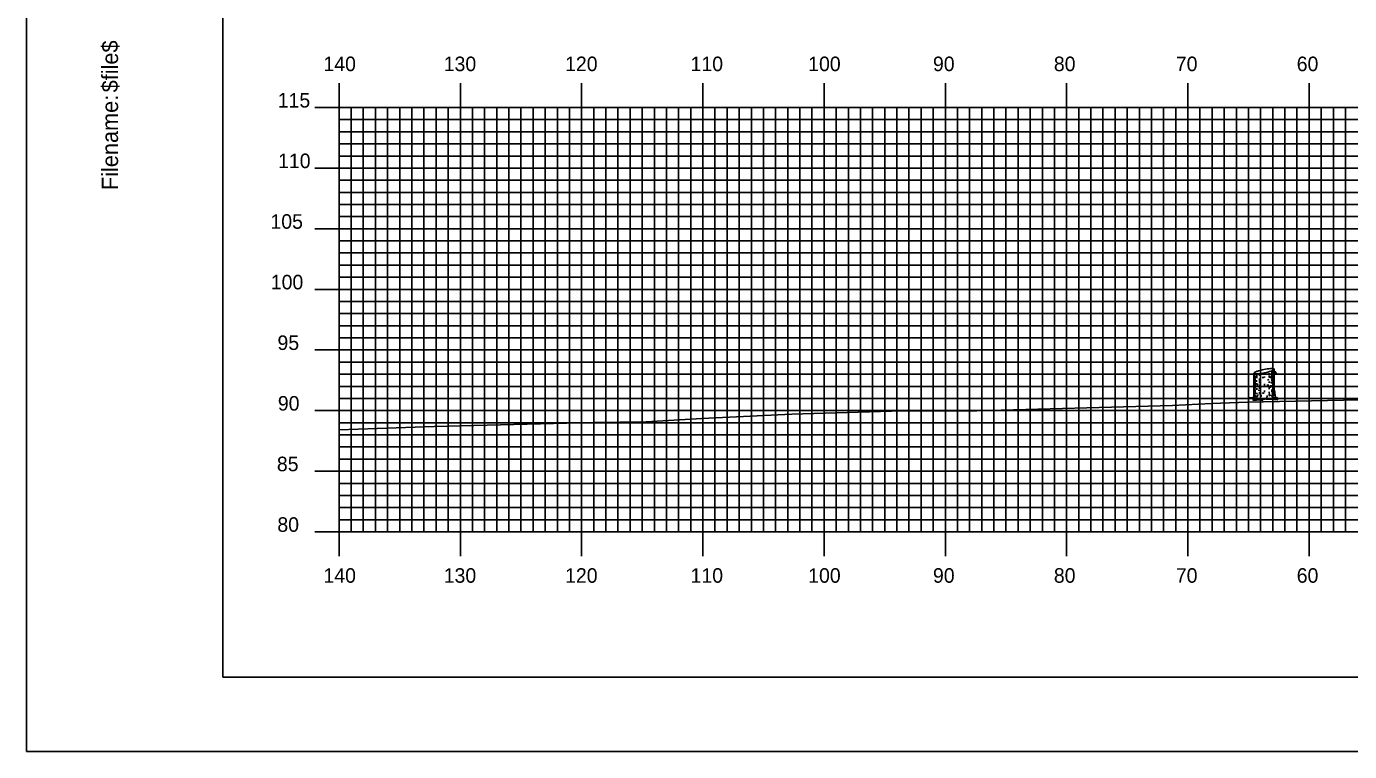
# Model space of a CAD drawing. Extents: x 1760610 to 1760954, y 442591 to 442811.
# Drawn here: x 1760610.4 to 1760719.5, y 442590.5 to 442650.4 of the extents above; entities that cross this region are included whole.
import ezdxf

# ---------------------------------------------------------------- set-up
doc = ezdxf.new("R2010")
doc.units = 0
for name, color, linetype in [('BORDER', 7, 'Continuous'), ('H_V ANNOTATION', 7, 'Continuous'), ('M_Trees_Conifer_Pay', 7, 'Continuous'), ('MAJOR', 7, 'Continuous'), ('MINOR', 7, 'Continuous'), ('PLOT BOUNDARY', 7, 'Continuous'), ('S_Roadway_Centerline', 7, 'Continuous')]:
    doc.layers.add(name, color=color, linetype=linetype)

msp = doc.modelspace()

# ---------------------------------------------------------------- linework, layer by layer
at = {"layer": 'BORDER'}
msp.add_lwpolyline([(1760626.61, 442596.67), (1760946.61, 442596.67), (1760946.61, 442806.67), (1760626.61, 442806.67)], close=True, dxfattribs=at)
at = {"layer": 'M_Trees_Conifer_Pay'}
for p, q in [((1760713.26, 442622.01), (1760713.26, 442621.85)), ((1760713.33, 442620.44), (1760713.33, 442622.09)), ((1760711.66, 442620.03), (1760711.66, 442621.75)), ((1760711.71, 442621.71), (1760711.71, 442621.24)), ((1760711.71, 442621.18), (1760711.71, 442620.87)), ((1760711.77, 442621.7), (1760711.77, 442621.61)), ((1760711.77, 442621.53), (1760711.77, 442621.33)), ((1760711.77, 442621.27), (1760711.77, 442621.07)), ((1760711.77, 442621.02), (1760711.77, 442620.69)), ((1760711.89, 442621.7), (1760711.89, 442621.46)), ((1760711.89, 442621.42), (1760711.89, 442621.35)), ((1760711.89, 442620.94), (1760711.89, 442620.81)), ((1760712.11, 442621.72), (1760712.11, 442621.55)), ((1760712.11, 442621.31), (1760712.11, 442621.07)), ((1760712.52, 442621.48), (1760712.52, 442621.39)), ((1760712.91, 442621.76), (1760712.91, 442621.56)), ((1760712.91, 442621.5), (1760712.91, 442621.41)), ((1760712.91, 442621.06), (1760712.91, 442620.96)), ((1760713.14, 442621.95), (1760713.14, 442621.73)), ((1760713.14, 442621.64), (1760713.14, 442621.59)), ((1760713.2, 442621.46), (1760713.14, 442621.4)), ((1760713.14, 442621.26), (1760713.14, 442621.13)), ((1760713.14, 442621.02), (1760713.14, 442620.91)), ((1760713.26, 442621.78), (1760713.26, 442621.66)), ((1760713.26, 442621.47), (1760713.26, 442621.13)), ((1760713.26, 442621.1), (1760713.26, 442620.93)), ((1760713.26, 442620.89), (1760713.26, 442620.67)), ((1760711.71, 442620.82), (1760711.71, 442620.33)), ((1760711.71, 442620.28), (1760711.71, 442620.03)), ((1760711.77, 442620.63), (1760711.77, 442620.5)), ((1760711.77, 442620.4), (1760711.77, 442620.02)), ((1760711.89, 442620.53), (1760711.89, 442620.39)), ((1760711.89, 442620.13), (1760711.89, 442620.04)), ((1760712.11, 442620.83), (1760712.11, 442620.68)), ((1760712.11, 442620.63), (1760712.11, 442620.46)), ((1760712.11, 442620.18), (1760712.11, 442620.03)), ((1760712.52, 442620.87), (1760712.52, 442620.8)), ((1760712.52, 442620.77), (1760712.52, 442620.62)), ((1760712.52, 442620.33), (1760712.52, 442620.18)), ((1760712.91, 442620.59), (1760712.91, 442620.45)), ((1760712.91, 442620.21), (1760712.91, 442620.12)), ((1760713.14, 442620.77), (1760713.14, 442620.63)), ((1760713.14, 442620.4), (1760713.14, 442620.23)), ((1760713.26, 442620.64), (1760713.26, 442620.57)), ((1760713.26, 442620.52), (1760713.26, 442620.35)), ((1760711.89, 442619.64), (1760712.06, 442619.7)), ((1760712.33, 442619.57), (1760712.21, 442619.64))]:
    msp.add_line(p, q, dxfattribs=at)
for points in [[(1760711.84, 442621.06), (1760711.84, 442621.15), (1760711.88, 442621.13), (1760711.88, 442621.04)], [(1760713.11, 442621.55), (1760713.08, 442621.46), (1760713.08, 442621.4), (1760713.11, 442621.33)], [(1760713.14, 442621.58), (1760713.18, 442621.51), (1760713.23, 442621.57), (1760713.29, 442621.64), (1760713.38, 442621.83), (1760713.44, 442621.88), (1760713.47, 442621.88)], [(1760713.16, 442621.33), (1760713.2, 442621.46), (1760713.26, 442621.57), (1760713.29, 442621.64), (1760713.36, 442621.79)], [(1760713.37, 442621.82), (1760713.45, 442621.83), (1760713.52, 442621.73)], [(1760713.33, 442620.44), (1760713.38, 442620.18), (1760713.4, 442619.9), (1760713.45, 442619.78), (1760713.59, 442619.75), (1760713.36, 442619.71), (1760713.36, 442619.71), (1760713.36, 442619.66), (1760713.61, 442619.57), (1760713.34, 442619.59), (1760712.98, 442619.61), (1760712.66, 442619.6), (1760712.67, 442619.68), (1760712.52, 442619.6), (1760712.33, 442619.57), (1760712.36, 442619.5), (1760712.09, 442619.55), (1760711.87, 442619.52), (1760711.58, 442619.54), (1760711.86, 442619.6), (1760711.89, 442619.64), (1760711.73, 442619.69), (1760711.5, 442619.71), (1760711.25, 442619.71), (1760711.6, 442619.76), (1760711.64, 442619.84), (1760711.66, 442620.03)], [(1760711.71, 442619.98), (1760711.69, 442619.9), (1760711.67, 442619.81)], [(1760711.79, 442619.96), (1760711.8, 442619.85), (1760711.74, 442619.76), (1760711.73, 442619.69)], [(1760711.95, 442619.99), (1760711.95, 442619.86), (1760711.86, 442619.76)], [(1760712.18, 442619.75), (1760712.25, 442619.84), (1760712.27, 442619.98)], [(1760712.67, 442619.68), (1760712.74, 442619.82), (1760712.75, 442619.92)], [(1760712.92, 442620.05), (1760712.93, 442619.92), (1760713, 442619.88)], [(1760712.98, 442620.66), (1760712.99, 442620.58), (1760713.04, 442620.59), (1760713.03, 442620.76)], [(1760713.2, 442619.66), (1760713.18, 442619.8), (1760713.11, 442619.92)], [(1760713.15, 442620.15), (1760713.23, 442620.05), (1760713.23, 442619.87), (1760713.36, 442619.71)], [(1760713.25, 442620.3), (1760713.26, 442620.15), (1760713.31, 442620.08), (1760713.32, 442619.88)]]:
    msp.add_lwpolyline(points, dxfattribs=at)
for centre, radius, start, end in [((1760713.52, 442616.98), 5.18, 101.7194, 108.0594), ((1760713.52, 442616.98), 5.18, 95.3794, 101.7194), ((1760713.11, 442621.34), 0.802, 79.2194, 95.3794), ((1760712.83, 442622.69), 0.802, 288.0594, 304.2194), ((1760713.21, 442621.88), 0.251, 71.0501, 79.2194), ((1760713.14, 442622.24), 0.251, 304.2194, 312.3887), ((1760713.27, 442622.04), 0.0817, 56.7194, 71.0501), ((1760713.28, 442622.07), 0.0527, 46.923, 56.7194), ((1760713.25, 442622.11), 0.0817, 312.3887, 326.7194), ((1760713.3, 442622.08), 0.0314, 34.2194, 46.923), ((1760713.3, 442622.09), 0.0264, 23.4074, 34.2194), ((1760713.28, 442622.1), 0.0527, 326.7194, 336.5158), ((1760713.31, 442622.09), 0.0226, 11.7194, 23.4074), ((1760713.3, 442622.09), 0.0264, 349.2194, 0.0315), ((1760713.31, 442622.09), 0.0226, 0.0315, 11.7194), ((1760713.3, 442622.09), 0.0314, 336.5158, 349.2194), ((1760711.7, 442621.75), 0.0314, 156.5158, 169.2194), ((1760711.69, 442621.75), 0.0264, 169.2194, 180.0315), ((1760711.69, 442621.75), 0.0226, 180.0315, 191.7194), ((1760711.69, 442621.75), 0.0226, 191.7194, 203.4074), ((1760711.7, 442621.57), 0.0334, 163.9485, 180), ((1760711.7, 442621.57), 0.0334, 180, 196.0515), ((1760711.71, 442621.58), 0.0441, 196.0515, 210), ((1760711.7, 442621.13), 0.0334, 163.9485, 180), ((1760711.7, 442621.13), 0.0334, 180, 196.0515), ((1760711.71, 442621.13), 0.0441, 196.0515, 210), ((1760711.7, 442620.92), 0.0334, 163.9485, 180), ((1760711.7, 442620.92), 0.0334, 180, 196.0515), ((1760711.71, 442620.92), 0.0441, 196.0515, 210), ((1760711.74, 442621.73), 0.0817, 132.3887, 146.7194), ((1760711.72, 442621.74), 0.0527, 146.7194, 156.5158), ((1760711.69, 442621.75), 0.0264, 203.4074, 214.2194), ((1760711.69, 442621.76), 0.0314, 214.2194, 226.923), ((1760711.71, 442621.77), 0.0527, 226.923, 236.7194), ((1760711.72, 442621.59), 0.0624, 210, 228.7494), ((1760711.72, 442621.14), 0.0624, 210, 228.7494), ((1760711.72, 442620.93), 0.0624, 210, 228.7494), ((1760711.85, 442621.6), 0.251, 124.2194, 132.3887), ((1760711.72, 442621.8), 0.0817, 236.7194, 251.0501), ((1760711.79, 442621.67), 0.172, 228.7494, 240), ((1760711.79, 442621.22), 0.172, 228.7494, 240), ((1760711.78, 442621.96), 0.251, 251.0501, 259.2194), ((1760712.16, 442621.15), 0.802, 108.0594, 124.2194), ((1760711.99, 442622.01), 0.571, 240, 240.3367), ((1760712, 442621.8), 0.571, 240, 247.0587), ((1760711.99, 442621.57), 0.571, 240, 240.3367), ((1760711.88, 442622.5), 0.802, 259.2194, 275.3794), ((1760711.99, 442622.01), 0.571, 246.8597, 257.9846), ((1760711.47, 442626.85), 5.18, 275.3794, 281.7194), ((1760712.49, 442625.08), 4.12, 264.081, 266.6676), ((1760712.5, 442625.76), 4.12, 264.6955, 266.7331), ((1760712.49, 442625.53), 4.12, 268.0751, 270), ((1760712.49, 442625.53), 4.12, 270, 270.3581), ((1760711.47, 442626.85), 5.18, 281.7194, 288.0594), ((1760712.5, 442625.32), 4.12, 273.7052, 275.9504), ((1760712.49, 442625.53), 4.12, 275.7849, 277.0558), ((1760712.5, 442625.76), 4.12, 276.238, 278.1032), ((1760712.49, 442625.08), 4.12, 277.6125, 278.1032), ((1760713, 442622.25), 0.571, 278.1032, 284.3667), ((1760713, 442621.57), 0.571, 278.1032, 286.9296), ((1760713, 442622.4), 0.571, 284.4317, 292.4132), ((1760713, 442621.8), 0.571, 284.4493, 297.0429), ((1760713, 442622.25), 0.571, 297.0237, 300), ((1760713, 442621.57), 0.571, 297.1896, 300), ((1760713.2, 442622.06), 0.172, 300, 311.2506), ((1760713.2, 442621.9), 0.172, 300, 311.2506), ((1760713.19, 442621.22), 0.172, 300, 311.2506), ((1760713.27, 442621.97), 0.0624, 311.2506, 330), ((1760713.27, 442621.82), 0.0624, 311.2506, 330), ((1760713.27, 442621.14), 0.0624, 311.2506, 330), ((1760713.27, 442620.93), 0.0624, 311.2506, 330), ((1760713.28, 442621.96), 0.0441, 330, 343.9485), ((1760713.28, 442621.81), 0.0441, 330, 343.9485), ((1760713.28, 442621.13), 0.0441, 330, 343.9485), ((1760713.28, 442620.92), 0.0441, 330, 343.9485), ((1760713.29, 442621.96), 0.0334, 343.9485, 354.2151), ((1760713.29, 442621.81), 0.0334, 343.9485, 354.2151), ((1760713.29, 442621.36), 0.0334, 343.9485, 354.2151), ((1760713.29, 442621.13), 0.0334, 343.9485, 354.2151), ((1760713.29, 442620.92), 0.0334, 343.9485, 354.2151), ((1760711.7, 442620.68), 0.0334, 163.9485, 180), ((1760711.7, 442620.68), 0.0334, 180, 196.0515), ((1760711.71, 442620.68), 0.0441, 196.0515, 210), ((1760711.7, 442620.48), 0.0334, 163.9485, 180), ((1760711.7, 442620.29), 0.0334, 163.9485, 180), ((1760711.7, 442620.29), 0.0334, 180, 196.0515), ((1760711.71, 442620.29), 0.0441, 196.0515, 210), ((1760711.7, 442620.07), 0.0334, 163.9485, 180), ((1760711.7, 442620.07), 0.0334, 180, 196.0515), ((1760711.71, 442620.07), 0.0441, 196.0515, 210), ((1760711.72, 442620.69), 0.0624, 210, 228.7494), ((1760711.72, 442620.3), 0.0624, 210, 228.7494), ((1760711.72, 442620.08), 0.0624, 210, 228.7494), ((1760711.79, 442621.01), 0.172, 228.7494, 240), ((1760711.79, 442620.77), 0.172, 228.7494, 240), ((1760711.79, 442620.38), 0.172, 228.7494, 240), ((1760711.79, 442620.16), 0.172, 228.7494, 240), ((1760711.99, 442621.36), 0.571, 240, 246.8597), ((1760711.99, 442621.12), 0.571, 240, 246.8597), ((1760711.98, 442620.93), 0.571, 241.2369, 248.0268), ((1760711.99, 442620.73), 0.571, 240, 246.8597), ((1760711.99, 442620.51), 0.571, 240, 244.5314), ((1760711.99, 442621.36), 0.571, 259.2707, 261.8968), ((1760712.49, 442624.87), 4.12, 261.8968, 263.1474), ((1760712.49, 442624.02), 4.12, 262.4438, 263.512), ((1760712.49, 442624.44), 4.12, 263.4991, 265.8397), ((1760712.49, 442624.64), 4.12, 264.716, 266.3193), ((1760712.49, 442624.24), 4.12, 267.8117, 270), ((1760712.49, 442624.87), 4.12, 270, 270.3581), ((1760712.49, 442624.24), 4.12, 270, 270.1328), ((1760712.49, 442624.87), 4.12, 273.1493, 275.4569), ((1760712.49, 442624.24), 4.12, 275.7849, 276.7896), ((1760712.49, 442624.02), 4.12, 277.3684, 278.1032), ((1760713, 442620.51), 0.571, 278.1032, 281.637), ((1760713, 442621.12), 0.571, 285.3983, 297.1896), ((1760713, 442620.92), 0.571, 289.2907, 300), ((1760713, 442620.73), 0.571, 288.5067, 297.2721), ((1760713, 442621.36), 0.571, 297.1896, 300), ((1760713.19, 442621.01), 0.172, 300, 311.2506), ((1760713.19, 442620.58), 0.172, 300, 311.2506), ((1760713.19, 442620.16), 0.172, 300, 311.2506), ((1760713.27, 442620.49), 0.0624, 311.2506, 330), ((1760713.27, 442620.08), 0.0624, 311.2506, 330), ((1760713.28, 442620.49), 0.0441, 330, 343.9485), ((1760713.28, 442620.07), 0.0441, 330, 343.9485), ((1760713.29, 442620.48), 0.0334, 343.9485, 354.2151), ((1760713.29, 442620.07), 0.0334, 343.9485, 354.2151)]:
    msp.add_arc(centre, radius, start, end, dxfattribs=at)
at = {"layer": 'MAJOR'}
for p, q in [((1760636.21, 442645.67), (1760636.21, 442643.67)), ((1760646.21, 442645.67), (1760646.21, 442643.67)), ((1760656.21, 442645.67), (1760656.21, 442643.67)), ((1760666.21, 442645.67), (1760666.21, 442643.67)), ((1760676.21, 442645.67), (1760676.21, 442643.67)), ((1760686.21, 442645.67), (1760686.21, 442643.67)), ((1760696.21, 442645.67), (1760696.21, 442643.67)), ((1760706.21, 442645.67), (1760706.21, 442643.67)), ((1760716.21, 442645.67), (1760716.21, 442643.67)), ((1760634.21, 442643.67), (1760636.21, 442643.67)), ((1760636.21, 442643.67), (1760916.21, 442643.67)), ((1760636.21, 442608.67), (1760636.21, 442643.67)), ((1760636.21, 442608.67), (1760636.21, 442643.67)), ((1760636.21, 442643.67), (1760916.21, 442643.67)), ((1760646.21, 442608.67), (1760646.21, 442643.67)), ((1760656.21, 442608.67), (1760656.21, 442643.67)), ((1760666.21, 442608.67), (1760666.21, 442643.67)), ((1760676.21, 442608.67), (1760676.21, 442643.67)), ((1760686.21, 442608.67), (1760686.21, 442643.67)), ((1760696.21, 442608.67), (1760696.21, 442643.67)), ((1760706.21, 442608.67), (1760706.21, 442643.67)), ((1760716.21, 442608.67), (1760716.21, 442643.67)), ((1760634.21, 442638.67), (1760636.21, 442638.67)), ((1760636.21, 442638.67), (1760916.21, 442638.67)), ((1760634.21, 442633.67), (1760636.21, 442633.67)), ((1760636.21, 442633.67), (1760916.21, 442633.67)), ((1760634.21, 442628.67), (1760636.21, 442628.67)), ((1760636.21, 442628.67), (1760916.21, 442628.67)), ((1760634.21, 442623.67), (1760636.21, 442623.67)), ((1760636.21, 442623.67), (1760916.21, 442623.67)), ((1760634.21, 442618.67), (1760636.21, 442618.67)), ((1760636.21, 442618.67), (1760916.21, 442618.67)), ((1760634.21, 442613.67), (1760636.21, 442613.67)), ((1760636.21, 442613.67), (1760916.21, 442613.67)), ((1760634.21, 442608.67), (1760636.21, 442608.67)), ((1760636.21, 442608.67), (1760916.21, 442608.67)), ((1760636.21, 442608.67), (1760916.21, 442608.67)), ((1760636.21, 442606.66), (1760636.21, 442608.67)), ((1760646.21, 442606.66), (1760646.21, 442608.67)), ((1760656.21, 442606.66), (1760656.21, 442608.67)), ((1760666.21, 442606.66), (1760666.21, 442608.67)), ((1760676.21, 442606.66), (1760676.21, 442608.67)), ((1760686.21, 442606.66), (1760686.21, 442608.67)), ((1760696.21, 442606.66), (1760696.21, 442608.67)), ((1760706.21, 442606.66), (1760706.21, 442608.67)), ((1760716.21, 442606.66), (1760716.21, 442608.67))]:
    msp.add_line(p, q, dxfattribs=at)
at = {"layer": 'MINOR'}
for p, q in [((1760637.21, 442608.67), (1760637.21, 442643.67)), ((1760638.21, 442608.67), (1760638.21, 442643.67)), ((1760639.21, 442608.67), (1760639.21, 442643.67)), ((1760640.21, 442608.67), (1760640.21, 442643.67)), ((1760641.21, 442608.67), (1760641.21, 442643.67)), ((1760642.21, 442608.67), (1760642.21, 442643.67)), ((1760643.21, 442608.67), (1760643.21, 442643.67)), ((1760644.21, 442608.67), (1760644.21, 442643.67)), ((1760645.21, 442608.67), (1760645.21, 442643.67)), ((1760647.21, 442608.67), (1760647.21, 442643.67)), ((1760648.21, 442608.67), (1760648.21, 442643.67)), ((1760649.21, 442608.67), (1760649.21, 442643.67)), ((1760650.21, 442608.67), (1760650.21, 442643.67)), ((1760651.21, 442608.67), (1760651.21, 442643.67)), ((1760652.21, 442608.67), (1760652.21, 442643.67)), ((1760653.21, 442608.67), (1760653.21, 442643.67)), ((1760654.21, 442608.67), (1760654.21, 442643.67)), ((1760655.21, 442608.67), (1760655.21, 442643.67)), ((1760657.21, 442608.67), (1760657.21, 442643.67)), ((1760658.21, 442608.67), (1760658.21, 442643.67)), ((1760659.21, 442608.67), (1760659.21, 442643.67)), ((1760660.21, 442608.67), (1760660.21, 442643.67)), ((1760661.21, 442608.67), (1760661.21, 442643.67)), ((1760662.21, 442608.67), (1760662.21, 442643.67)), ((1760663.21, 442608.67), (1760663.21, 442643.67)), ((1760664.21, 442608.67), (1760664.21, 442643.67)), ((1760665.21, 442608.67), (1760665.21, 442643.67)), ((1760667.21, 442608.67), (1760667.21, 442643.67)), ((1760668.21, 442608.67), (1760668.21, 442643.67)), ((1760669.21, 442608.67), (1760669.21, 442643.67)), ((1760670.21, 442608.67), (1760670.21, 442643.67)), ((1760671.21, 442608.67), (1760671.21, 442643.67)), ((1760672.21, 442608.67), (1760672.21, 442643.67)), ((1760673.21, 442608.67), (1760673.21, 442643.67)), ((1760674.21, 442608.67), (1760674.21, 442643.67)), ((1760675.21, 442608.67), (1760675.21, 442643.67)), ((1760677.21, 442608.67), (1760677.21, 442643.67)), ((1760678.21, 442608.67), (1760678.21, 442643.67)), ((1760679.21, 442608.67), (1760679.21, 442643.67)), ((1760680.21, 442608.67), (1760680.21, 442643.67)), ((1760681.21, 442608.67), (1760681.21, 442643.67)), ((1760682.21, 442608.67), (1760682.21, 442643.67)), ((1760683.21, 442608.67), (1760683.21, 442643.67)), ((1760684.21, 442608.67), (1760684.21, 442643.67)), ((1760685.21, 442608.67), (1760685.21, 442643.67)), ((1760687.21, 442608.67), (1760687.21, 442643.67)), ((1760688.21, 442608.67), (1760688.21, 442643.67)), ((1760689.21, 442608.67), (1760689.21, 442643.67)), ((1760690.21, 442608.67), (1760690.21, 442643.67)), ((1760691.21, 442608.67), (1760691.21, 442643.67)), ((1760692.21, 442608.67), (1760692.21, 442643.67)), ((1760693.21, 442608.67), (1760693.21, 442643.67)), ((1760694.21, 442608.67), (1760694.21, 442643.67)), ((1760695.21, 442608.67), (1760695.21, 442643.67)), ((1760697.21, 442608.67), (1760697.21, 442643.67)), ((1760698.21, 442608.67), (1760698.21, 442643.67)), ((1760699.21, 442608.67), (1760699.21, 442643.67)), ((1760700.21, 442608.67), (1760700.21, 442643.67)), ((1760701.21, 442608.67), (1760701.21, 442643.67)), ((1760702.21, 442608.67), (1760702.21, 442643.67)), ((1760703.21, 442608.67), (1760703.21, 442643.67)), ((1760704.21, 442608.67), (1760704.21, 442643.67)), ((1760705.21, 442608.67), (1760705.21, 442643.67)), ((1760707.21, 442608.67), (1760707.21, 442643.67)), ((1760708.21, 442608.67), (1760708.21, 442643.67)), ((1760709.21, 442608.67), (1760709.21, 442643.67)), ((1760710.21, 442608.67), (1760710.21, 442643.67)), ((1760711.21, 442608.67), (1760711.21, 442643.67)), ((1760712.21, 442608.67), (1760712.21, 442643.67)), ((1760713.21, 442608.67), (1760713.21, 442643.67)), ((1760714.21, 442608.67), (1760714.21, 442643.67)), ((1760715.21, 442608.67), (1760715.21, 442643.67)), ((1760717.21, 442608.67), (1760717.21, 442643.67)), ((1760718.21, 442608.67), (1760718.21, 442643.67)), ((1760719.21, 442608.67), (1760719.21, 442643.67)), ((1760636.21, 442642.67), (1760916.21, 442642.67)), ((1760636.21, 442642.67), (1760638.22, 442642.67)), ((1760636.21, 442641.67), (1760916.21, 442641.67)), ((1760636.21, 442641.67), (1760638.22, 442641.67)), ((1760636.21, 442640.67), (1760916.21, 442640.67)), ((1760636.21, 442640.67), (1760638.22, 442640.67)), ((1760636.21, 442639.67), (1760916.21, 442639.67)), ((1760636.21, 442639.67), (1760638.22, 442639.67)), ((1760636.21, 442637.67), (1760916.21, 442637.67)), ((1760636.21, 442637.67), (1760638.22, 442637.67)), ((1760636.21, 442636.67), (1760916.21, 442636.67)), ((1760636.21, 442636.67), (1760638.22, 442636.67)), ((1760636.21, 442635.67), (1760916.21, 442635.67)), ((1760636.21, 442635.67), (1760638.22, 442635.67)), ((1760636.21, 442634.67), (1760916.21, 442634.67)), ((1760636.21, 442634.67), (1760638.22, 442634.67)), ((1760636.21, 442632.67), (1760916.21, 442632.67)), ((1760636.21, 442632.67), (1760638.22, 442632.67)), ((1760636.21, 442631.67), (1760916.21, 442631.67)), ((1760636.21, 442631.67), (1760638.22, 442631.67)), ((1760636.21, 442630.67), (1760916.21, 442630.67)), ((1760636.21, 442630.67), (1760638.22, 442630.67)), ((1760636.21, 442629.67), (1760916.21, 442629.67)), ((1760636.21, 442629.67), (1760638.22, 442629.67)), ((1760636.21, 442627.67), (1760916.21, 442627.67)), ((1760636.21, 442627.67), (1760638.22, 442627.67)), ((1760636.21, 442626.67), (1760916.21, 442626.67)), ((1760636.21, 442626.67), (1760638.22, 442626.67)), ((1760636.21, 442625.67), (1760916.21, 442625.67)), ((1760636.21, 442625.67), (1760638.22, 442625.67)), ((1760636.21, 442624.67), (1760916.21, 442624.67)), ((1760636.21, 442624.67), (1760638.22, 442624.67)), ((1760636.21, 442622.67), (1760916.21, 442622.67)), ((1760636.21, 442622.67), (1760638.22, 442622.67)), ((1760636.21, 442621.67), (1760916.21, 442621.67)), ((1760636.21, 442621.67), (1760638.22, 442621.67)), ((1760636.21, 442620.67), (1760916.21, 442620.67)), ((1760636.21, 442620.67), (1760638.22, 442620.67)), ((1760636.21, 442619.67), (1760916.21, 442619.67)), ((1760636.21, 442619.67), (1760638.22, 442619.67)), ((1760636.21, 442617.67), (1760916.21, 442617.67)), ((1760636.21, 442617.67), (1760638.22, 442617.67)), ((1760636.21, 442616.67), (1760916.21, 442616.67)), ((1760636.21, 442616.67), (1760638.22, 442616.67)), ((1760636.21, 442615.67), (1760916.21, 442615.67)), ((1760636.21, 442615.67), (1760638.22, 442615.67)), ((1760636.21, 442614.67), (1760916.21, 442614.67)), ((1760636.21, 442614.67), (1760638.22, 442614.67)), ((1760636.21, 442612.67), (1760916.21, 442612.67)), ((1760636.21, 442612.67), (1760638.22, 442612.67)), ((1760636.21, 442611.67), (1760916.21, 442611.67)), ((1760636.21, 442611.67), (1760638.22, 442611.67)), ((1760636.21, 442610.67), (1760916.21, 442610.67)), ((1760636.21, 442610.67), (1760638.22, 442610.67)), ((1760636.21, 442609.67), (1760916.21, 442609.67)), ((1760636.21, 442609.67), (1760638.22, 442609.67))]:
    msp.add_line(p, q, dxfattribs=at)
at = {"layer": 'PLOT BOUNDARY'}
msp.add_lwpolyline([(1760610.43, 442590.55), (1760950.43, 442590.55), (1760950.43, 442810.55), (1760610.43, 442810.55)], close=True, dxfattribs=at)
at = {"layer": 'S_Roadway_Centerline'}
msp.add_lwpolyline([(1760636.21, 442617.08), (1760644.06, 442617.37), (1760657.18, 442617.69), (1760661.55, 442617.75), (1760666.13, 442618.03), (1760673.56, 442618.37), (1760681.77, 442618.62), (1760688.82, 442618.65), (1760704.94, 442619.1), (1760708.17, 442619.26), (1760711.14, 442619.36), (1760729.61, 442619.74)], dxfattribs=at)

# ---------------------------------------------------------------- texts
at = {"layer": 'BORDER'}
for s, p in [('$file$', (1760617.98, 442644.92)), ('Filename:', (1760617.98, 442636.86))]:
    msp.add_text(s, height=1.339, rotation=90, dxfattribs=at).set_placement(p)
at = {"layer": 'H_V ANNOTATION'}
for s, p in [('140', (1760634.92, 442646.67)), ('130', (1760644.84, 442646.67)), ('120', (1760654.85, 442646.67)), ('110', (1760665.2, 442646.67)), ('100', (1760674.9, 442646.67)), ('90', (1760685.19, 442646.67)), ('80', (1760695.16, 442646.67)), ('70', (1760705.22, 442646.67)), ('60', (1760715.19, 442646.67)), ('115', (1760631.15, 442643.67)), ('110', (1760631.18, 442638.67)), ('105', (1760630.55, 442633.67)), ('100', (1760630.58, 442628.67)), ('95', (1760631.13, 442623.67)), ('90', (1760631.16, 442618.67)), ('85', (1760631.08, 442613.67)), ('80', (1760631.12, 442608.67)), ('140', (1760634.92, 442604.47)), ('130', (1760644.84, 442604.47)), ('120', (1760654.85, 442604.47)), ('110', (1760665.2, 442604.47)), ('100', (1760674.9, 442604.47)), ('90', (1760685.19, 442604.47)), ('80', (1760695.16, 442604.47)), ('70', (1760705.22, 442604.47)), ('60', (1760715.19, 442604.47))]:
    msp.add_text(s, height=1.2, dxfattribs=at).set_placement(p)
at = {"layer": 'MAJOR'}
msp.add_text('-', height=0.012, dxfattribs=at).set_placement((1760636.2, 442608.67))

doc.saveas('drawing.dxf')
